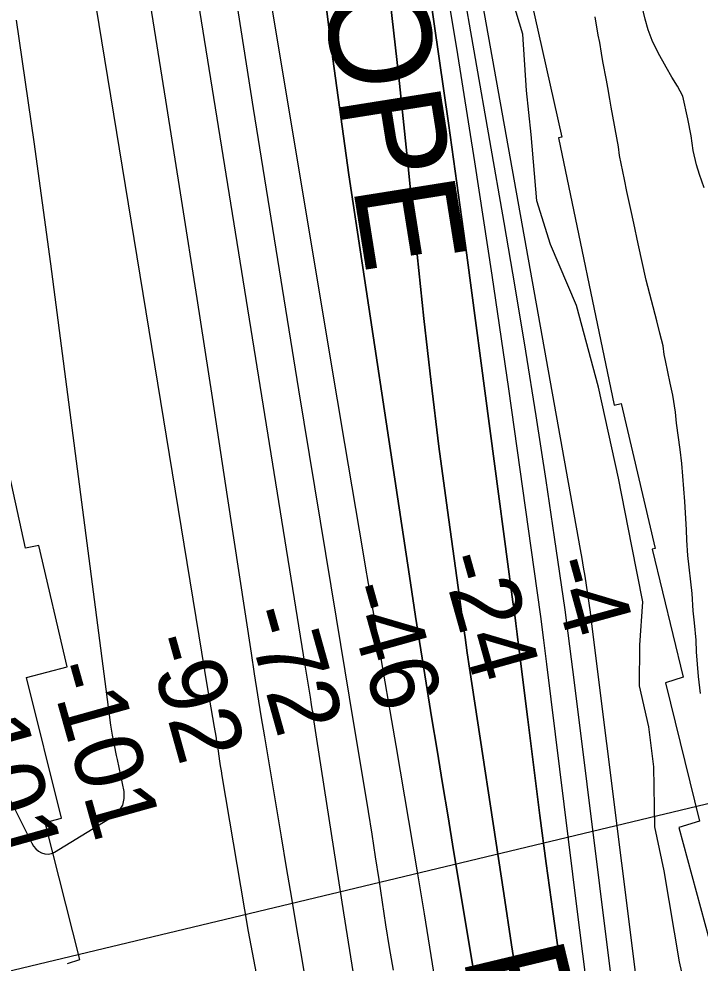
# Model space of a CAD drawing. Extents: x 3567028 to 3605064, y 510945 to 536587.
# Drawn here: x 3578355 to 3579024, y 532071 to 532999 of the extents above; entities that cross this region are included whole.
import ezdxf

# ---------------------------------------------------------------- set-up
doc = ezdxf.new("R2010")
doc.units = 0
for name, color, linetype in [('V-RIVR-EDGE', 7, 'Continuous'), ('V-RIVR-RANG', 7, 'Continuous'), ('V-RRAP-RVMT', 7, 'Continuous'), ('V-RRAP-RVMT-IDEN', 7, 'Continuous'), ('V-SITE-VEGE', 7, 'Continuous'), ('V-TOPO-DPTH', 7, 'Continuous'), ('V-TOPO-MAJR', 7, 'Continuous'), ('V-TOPO-MINR', 7, 'Continuous'), ('V-WETL-SWMP', 7, 'Continuous')]:
    doc.layers.add(name, color=color, linetype=linetype)

msp = doc.modelspace()

# ---------------------------------------------------------------- linework, layer by layer
at = {"layer": 'V-RIVR-EDGE'}
msp.add_lwpolyline([(3579013.1, 532031.24), (3579004, 532071.71), (3578988.91, 532161.2), (3578979.82, 532204.73), (3578978.74, 532263.55), (3578973.94, 532302.78), (3578964.85, 532343.24), (3578964.95, 532383.07), (3578968.12, 532425.95), (3578957.22, 532480.51), (3578943.91, 532547.33), (3578924.52, 532636.84), (3578902.66, 532717.16), (3578877.08, 532777.27), (3578863.7, 532820.19), (3578858.35, 532885.16), (3578853.55, 532928.67), (3578850.01, 532983.83), (3578833.61, 533038.4)], dxfattribs=at)
at = {"layer": 'V-RIVR-RANG'}
msp.add_line((3579599.9, 532363.51), (3578219.06, 532032.29), dxfattribs=at)
at = {"layer": 'V-RRAP-RVMT'}
for p, q in [((3578857.16, 533021.49), (3578888.22, 532882.57)), ((3578888.22, 532882.57), (3578885.1, 532881.98)), ((3578885.1, 532881.98), (3578939.87, 532619.27)), ((3578361.35, 532478.71), (3578328.18, 532629.87)), ((3578939.87, 532619.27), (3578946.74, 532620.76)), ((3578946.74, 532620.76), (3578980.18, 532478.33)), ((3578374.31, 532481.36), (3578361.35, 532478.71)), ((3578402.41, 532361.83), (3578374.31, 532481.36)), ((3578980.18, 532478.33), (3578976.98, 532477.73)), ((3578976.98, 532477.73), (3579007.68, 532351.84)), ((3578362.23, 532351.4), (3578402.41, 532361.83)), ((3579007.68, 532351.84), (3578990.35, 532346.29)), ((3578396.66, 532213.03), (3578362.23, 532351.4)), ((3578990.35, 532346.29), (3579023.72, 532210.13)), ((3578380.78, 532208.81), (3578396.66, 532213.03)), ((3578414.66, 532074.07), (3578380.78, 532208.81)), ((3579023.72, 532210.13), (3579003.37, 532203.92)), ((3579003.37, 532203.92), (3579037.31, 532078.21)), ((3578402.67, 532070.27), (3578414.66, 532074.07))]:
    msp.add_line(p, q, dxfattribs=at)
at = {"layer": 'V-SITE-VEGE'}
msp.add_lwpolyline([(3579024.47, 532335.72), (3579022.66, 532352.52), (3579020.84, 532376.51), (3579020.23, 532388.21), (3579018.72, 532405.31), (3579017.51, 532417.01), (3579016.3, 532434.1), (3579012.07, 532471.3), (3579011.16, 532486.3), (3579010.85, 532496.5), (3579009.33, 532524.39), (3579006.3, 532561.89), (3579004.79, 532575.69), (3579001.17, 532601.48), (3578999.96, 532612.28), (3578997.55, 532629.08), (3578994.85, 532640.77), (3578990.33, 532663.27), (3578988.83, 532668.97), (3578987.92, 532677.37), (3578984.61, 532689.96), (3578981.6, 532702.26), (3578971.37, 532742.15), (3578963.24, 532777.84), (3578959.03, 532798.24), (3578956.02, 532811.44), (3578952.11, 532829.43), (3578950, 532841.13), (3578945.18, 532864.82), (3578943.98, 532873.22), (3578936.75, 532912.21), (3578935.54, 532920.01), (3578933.43, 532931.41), (3578932.23, 532938.61), (3578928.62, 532957.2), (3578927.41, 532965.3), (3578925.6, 532975.8), (3578924.1, 532983), (3578921.08, 533001)], dxfattribs=at)
at = {"layer": 'V-TOPO-DPTH'}
for points in [[(3578963.08, 531846.66), (3578900.86, 532346.53), (3578896.28, 532382.28), (3578891.51, 532418), (3578886.48, 532453.69), (3578881.26, 532489.36), (3578872.89, 532545.17), (3578863.13, 532608.68), (3578853.06, 532672.15), (3578842.54, 532735.54), (3578831.71, 532798.88), (3578704.92, 533524.66), (3578702.95, 533536.69), (3578701.16, 533548.75), (3578699.64, 533560.84), (3578698.29, 533572.96), (3578696.78, 533587.9), (3578695.36, 533607.52), (3578694.66, 533627.13), (3578695.04, 533646.76), (3578696.14, 533666.39), (3578774.18, 534596.22)], [(3578659.4, 533714.31), (3578661.14, 533671.71), (3578664.46, 533629.13), (3578668.02, 533595.7), (3578671, 533569.89), (3578674.3, 533544.11), (3578678.06, 533518.39), (3578682.13, 533492.72), (3578716.98, 533285.3), (3578738.04, 533155.85), (3578758.22, 533026.26), (3578777.06, 532896.48), (3578795.02, 532766.56), (3578840.34, 532425.82), (3578841.74, 532415.18), (3578843.12, 532404.54), (3578844.47, 532393.89), (3578845.8, 532383.24), (3578854.81, 532310.12), (3578860.74, 532262.93), (3578866.81, 532215.75), (3578873.1, 532168.6), (3578879.54, 532121.47), (3578910.52, 531898.44)], [(3578910.52, 531898.44), (3578879.54, 532121.47), (3578873.1, 532168.6), (3578866.81, 532215.75), (3578860.74, 532262.93), (3578854.81, 532310.12), (3578845.8, 532383.24), (3578844.47, 532393.89), (3578843.12, 532404.54), (3578841.74, 532415.18), (3578840.34, 532425.82), (3578795.02, 532766.56), (3578777.06, 532896.48), (3578758.22, 533026.26), (3578738.04, 533155.85), (3578716.98, 533285.3), (3578682.13, 533492.72), (3578678.06, 533518.39), (3578674.3, 533544.11), (3578671, 533569.89), (3578668.02, 533595.7), (3578664.46, 533629.13), (3578661.14, 533671.71), (3578659.4, 533714.31)], [(3578648.87, 533073.8), (3578663.26, 532959.56), (3578679.23, 532845.5), (3578739.6, 532444.46), (3578744.63, 532411.54), (3578749.74, 532378.63), (3578755, 532345.74), (3578760.35, 532312.87), (3578765.77, 532280.01), (3578771.2, 532247.15), (3578776.64, 532214.3), (3578782.08, 532181.44), (3578798.97, 532079.45), (3578808.91, 532018.92)], [(3578808.91, 532018.92), (3578798.97, 532079.45), (3578782.08, 532181.44), (3578776.64, 532214.3), (3578771.2, 532247.15), (3578765.77, 532280.01), (3578760.35, 532312.87), (3578755, 532345.74), (3578749.74, 532378.63), (3578744.63, 532411.54), (3578739.6, 532444.46), (3578679.23, 532845.5), (3578663.26, 532959.56), (3578648.87, 533073.8)], [(3578719.63, 533016.75), (3578728.04, 532941.73), (3578736.02, 532866.66), (3578743.71, 532791.56), (3578746.13, 532767.18), (3578752.75, 532704.29), (3578759.84, 532641.45), (3578767.65, 532578.7), (3578775.93, 532516), (3578789.04, 532420.81), (3578791.15, 532405.76), (3578793.29, 532390.71), (3578795.5, 532375.67), (3578797.74, 532360.64), (3578831.26, 532139.01), (3578838.91, 532088.73), (3578846.63, 532038.46)], [(3578846.63, 532038.46), (3578838.91, 532088.73), (3578831.26, 532139.01), (3578797.74, 532360.64), (3578795.5, 532375.67), (3578793.29, 532390.71), (3578791.15, 532405.76), (3578789.04, 532420.81), (3578775.93, 532516), (3578767.65, 532578.7), (3578759.84, 532641.45), (3578752.75, 532704.29), (3578746.13, 532767.18), (3578743.71, 532791.56), (3578736.02, 532866.66), (3578728.04, 532941.73), (3578719.63, 533016.75)]]:
    msp.add_lwpolyline(points, dxfattribs=at)
at = {"layer": 'V-TOPO-MAJR'}
for points in [[(3578766.58, 532037.09), (3578760.08, 532078.15), (3578753.38, 532119.19), (3578746.53, 532160.2), (3578725.46, 532284.55), (3578718.39, 532326.28), (3578711.31, 532368.01), (3578704.23, 532409.73), (3578697.15, 532451.46), (3578696.81, 532453.46), (3578689.58, 532496.19), (3578682.37, 532538.92), (3578675.2, 532581.66), (3578668.05, 532624.4), (3578520.59, 533509.17)], [(3578335.12, 532252.82), (3578367.46, 532188.46), (3578369.34, 532185.53), (3578371.53, 532182.93), (3578374.2, 532180.83), (3578377.2, 532179.07), (3578380.42, 532178.15), (3578383.61, 532177.87), (3578386.74, 532178.53), (3578389.83, 532179.82), (3578448, 532215.47), (3578453.24, 532220.32), (3578456.95, 532225.81), (3578458.37, 532232.29), (3578458.28, 532239.42), (3578456.61, 532247.23), (3578454.94, 532255.04), (3578453.28, 532262.84), (3578451.61, 532270.65), (3578450.72, 532274.83), (3578448.74, 532284.74), (3578446.91, 532294.69), (3578445.33, 532304.68), (3578443.91, 532314.69), (3578386.34, 532758.27), (3578369.98, 532878.11), (3578352.57, 532997.78)]]:
    msp.add_lwpolyline(points, dxfattribs=at)
at = {"layer": 'V-TOPO-MINR'}
for points in [[(3578963.08, 531846.66), (3578900.86, 532346.53), (3578896.28, 532382.28), (3578891.51, 532418), (3578886.48, 532453.69), (3578881.26, 532489.36), (3578872.89, 532545.17), (3578863.13, 532608.68), (3578853.06, 532672.15), (3578842.54, 532735.54), (3578831.71, 532798.88), (3578704.92, 533524.66), (3578702.95, 533536.69), (3578701.16, 533548.75), (3578699.64, 533560.84), (3578698.29, 533572.96), (3578696.78, 533587.9), (3578695.36, 533607.52), (3578694.66, 533627.13), (3578695.04, 533646.76), (3578696.14, 533666.39), (3578774.18, 534596.22)], [(3579022.1, 531572.73), (3578917.64, 532406.89), (3578916.49, 532415.72), (3578915.28, 532424.55), (3578913.99, 532433.36), (3578912.63, 532442.17), (3578911.21, 532450.96), (3578909.75, 532459.75), (3578908.24, 532468.53), (3578906.69, 532477.3), (3578716.27, 533540.73), (3578715.41, 533545.9), (3578714.63, 533551.08), (3578713.98, 533556.28), (3578713.4, 533561.49), (3578712.79, 533567.79), (3578712.2, 533576.15), (3578711.91, 533584.53), (3578712.09, 533592.9), (3578712.57, 533601.28), (3578797.42, 534596.41)], [(3578638.23, 532044.59), (3578633.06, 532074.58), (3578628.04, 532104.6), (3578623.01, 532134.62), (3578617.98, 532164.64), (3578612.95, 532194.65), (3578596.45, 532293.12), (3578593.05, 532313.7), (3578589.71, 532334.29), (3578586.47, 532354.89), (3578583.29, 532375.5), (3578559.92, 532529.25), (3578545, 532626.72), (3578529.93, 532724.18), (3578514.66, 532821.6), (3578499.24, 532919), (3578410.17, 533477.9), (3578408.43, 533488.99), (3578406.72, 533500.09), (3578405.06, 533511.19), (3578403.43, 533522.3), (3578383.91, 533657.7), (3578373.99, 533736.63)], [(3578910.52, 531898.44), (3578879.54, 532121.47), (3578873.1, 532168.6), (3578866.81, 532215.75), (3578860.74, 532262.93), (3578854.81, 532310.12), (3578845.8, 532383.24), (3578844.47, 532393.89), (3578843.12, 532404.54), (3578841.74, 532415.18), (3578840.34, 532425.82), (3578795.02, 532766.56), (3578777.06, 532896.48), (3578758.22, 533026.26), (3578738.04, 533155.85), (3578716.98, 533285.3), (3578682.13, 533492.72), (3578678.06, 533518.39), (3578674.3, 533544.11), (3578671, 533569.89), (3578668.02, 533595.7), (3578664.46, 533629.13), (3578661.14, 533671.71), (3578659.4, 533714.31)], [(3578911.64, 532059.2), (3578903.55, 532123.53), (3578873.71, 532364.62), (3578870.75, 532388), (3578867.72, 532411.37), (3578864.56, 532434.73), (3578861.32, 532458.08), (3578836.28, 532635.12), (3578819.98, 532746.91), (3578803.03, 532858.6), (3578785.12, 532970.13), (3578766.56, 533081.57), (3578693.52, 533508.65), (3578690.49, 533527.52), (3578687.71, 533546.42), (3578685.3, 533565.38), (3578683.15, 533584.37), (3578680.68, 533608.34), (3578678.35, 533639.34), (3578677.16, 533670.36), (3578677.71, 533701.4)], [(3578595.78, 532020.86), (3578580.51, 532101.81), (3578554.62, 532254.71), (3578553.82, 532259.57), (3578553.05, 532264.43), (3578552.33, 532269.29), (3578551.65, 532274.17), (3578550.96, 532279.04), (3578550.23, 532283.9), (3578549.45, 532288.76), (3578548.63, 532293.61), (3578547.04, 532302.74), (3578545.41, 532312.16), (3578543.8, 532321.58), (3578542.22, 532331), (3578540.66, 532340.43), (3578410.48, 533136.19), (3578400.83, 533195.04), (3578391.15, 533253.88), (3578381.43, 533312.72), (3578371.69, 533371.55), (3578355.76, 533467.48), (3578353.91, 533478.33)], [(3578684.62, 532054.13), (3578674.01, 532119.95), (3578647.65, 532290.92), (3578647, 532295.17), (3578646.36, 532299.42), (3578645.74, 532303.68), (3578645.12, 532307.94), (3578644.5, 532312.19), (3578643.86, 532316.45), (3578643.2, 532320.7), (3578642.51, 532324.95), (3578641.33, 532332.17), (3578640.04, 532340.03), (3578638.76, 532347.89), (3578637.48, 532355.76), (3578636.22, 532363.62), (3578510.08, 533148.01)], [(3578808.91, 532018.92), (3578798.97, 532079.45), (3578782.08, 532181.44), (3578776.64, 532214.3), (3578771.2, 532247.15), (3578765.77, 532280.01), (3578760.35, 532312.87), (3578755, 532345.74), (3578749.74, 532378.63), (3578744.63, 532411.54), (3578739.6, 532444.46), (3578679.23, 532845.5), (3578663.26, 532959.56), (3578648.87, 533073.8)], [(3578722.87, 532063.82), (3578719.16, 532086.03), (3578715.55, 532108.26), (3578712.09, 532130.51), (3578708.74, 532152.78), (3578705.39, 532175.05), (3578701.97, 532197.3), (3578698.42, 532219.54), (3578694.8, 532241.77), (3578684.1, 532306.26), (3578679.8, 532332.17), (3578675.52, 532358.08), (3578671.24, 532384), (3578666.98, 532409.91), (3578630.06, 532634.41), (3578607.57, 532772.61), (3578585.36, 532910.86), (3578563.61, 533049.17)], [(3578846.63, 532038.46), (3578838.91, 532088.73), (3578831.26, 532139.01), (3578797.74, 532360.64), (3578795.5, 532375.67), (3578793.29, 532390.71), (3578791.15, 532405.76), (3578789.04, 532420.81), (3578775.93, 532516), (3578767.65, 532578.7), (3578759.84, 532641.45), (3578752.75, 532704.29), (3578746.13, 532767.18), (3578743.71, 532791.56), (3578736.02, 532866.66), (3578728.04, 532941.73), (3578719.63, 533016.75)]]:
    msp.add_lwpolyline(points, dxfattribs=at)
at = {"layer": 'V-WETL-SWMP'}
for p, q in [((3578970.16, 532998.79), (3578965.81, 533018.31)), ((3578973.05, 532988.31), (3578970.16, 532998.79)), ((3578977.12, 532977.7), (3578973.05, 532988.31)), ((3578983.16, 532965.51), (3578977.12, 532977.7)), ((3578990.77, 532951.5), (3578983.16, 532965.51)), ((3578996.54, 532941.81), (3578990.77, 532951.5)), ((3579001.92, 532932.9), (3578996.54, 532941.81)), ((3579007.3, 532923.08), (3579001.92, 532932.9)), ((3579012.17, 532900.67), (3579007.3, 532923.08)), ((3579015.46, 532884.03), (3579012.17, 532900.67)), ((3579017.44, 532869.49), (3579015.46, 532884.03)), ((3579020.72, 532855.34), (3579017.44, 532869.49)), ((3579023.61, 532845.91), (3579020.72, 532855.34)), ((3579028.34, 532832.94), (3579023.61, 532845.91))]:
    msp.add_line(p, q, dxfattribs=at)

# ---------------------------------------------------------------- texts
at = {"layer": 'V-RIVR-RANG'}
for s, rotation, p in [('-24', 285.63, (3578768.34, 532468.03)), ('-4', 285.34833, (3578873.57, 532463.96)), ('-46', 285.63, (3578672.75, 532438.53)), ('-72', 285.63, (3578575.53, 532414.87)), ('-92', 285.63, (3578479.31, 532387.66)), ('-101', 285.63, (3578383.01, 532360.7)), ('-101', 285.63, (3578286.64, 532334))]:
    msp.add_text(s, height=67, rotation=rotation, dxfattribs=at).set_placement(p)
at = {"layer": 'V-RRAP-RVMT-IDEN'}
for s, rotation, p in [('HOPE', 279.03376, (3578637.25, 533121.06)), ('REV.', 283.47965, (3578790.45, 532076.92))]:
    msp.add_text(s, height=100, rotation=rotation, dxfattribs=at).set_placement(p)

doc.saveas('drawing.dxf')
